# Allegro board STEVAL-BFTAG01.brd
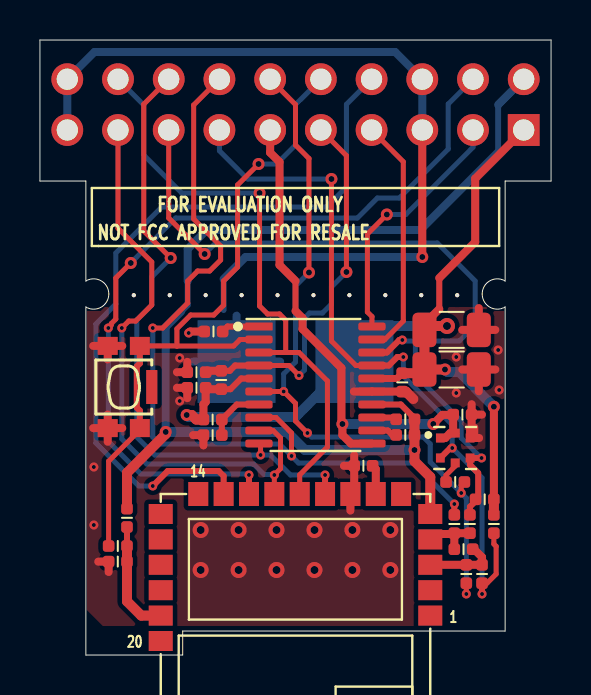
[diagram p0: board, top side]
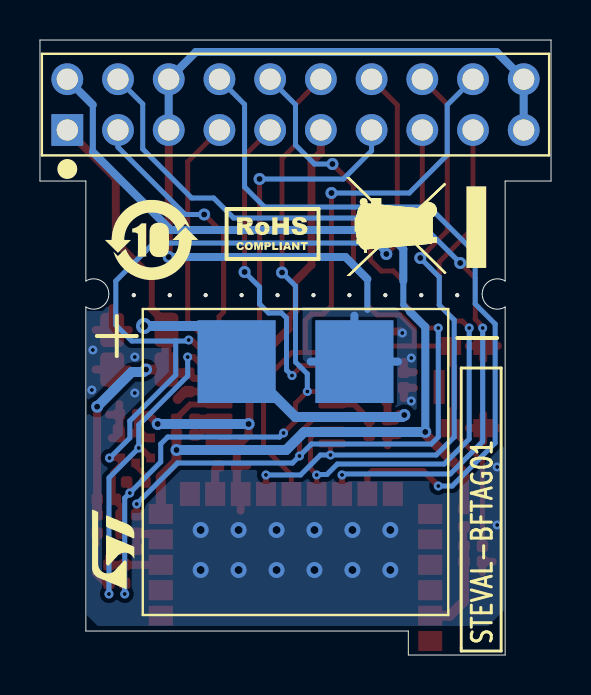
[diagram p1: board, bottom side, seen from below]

Outline 25.6 x 30.75 mm; copper layers: TOP, BOTTOM. Coordinates in mm from the lower left corner of the outline.
Outline path: 0,30.75 0,23.7 2.3,23.7 2.3,18.7 arc(3.06,18.71) 3.45,18.05 arc(3.06,17.39) 2.3,17.4 2.3,0 7.15,0 7.15,1.2 23.3,1.2 23.3,17.4 arc(22.54,17.39) 22.15,18.05 arc(22.54,18.71) 23.3,18.7 23.3,23.7 25.6,23.7 25.6,30.75 0,30.75

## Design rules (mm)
constraint set DEFAULT: min track width 0.4

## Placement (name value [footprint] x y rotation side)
B1  AM-1606C-MEL  [SOLAR_PANEL_AM-1606C-MEL]  12.8 9.65 0 bottom
CB1  100nF  [C_0402]  3.9 4.67 180 top
CH1  100nF  [C_0402]  21.16 12.02 0 top
CM1  10nF  [C_0402]  7.84 14.14 180 top
CM2  100nF  [C_0402]  7.84 13.36 180 top
CM3  100nF  [C_0402]  18.14 13.63 270 top
CS1  220uF  [C_1206_HD]  20.62 14.28 0 top
CS2  220uF  [C_1206_HD]  20.62 16.26 0 top
JSWD  con20-2x10-strip-male  [HDRV20W64P254_10X2_2540X508H838]  24.23 26.25 180 bottom
LOGO1  ST LOGO  [STLOGO12MM]  21.75 5.4 90 bottom
LOGO2  RoHS EU LOGO  [ROHS-EU-LOGO13MM]  16.25 19.1 180 bottom
LOGO3  ROHS_CH_LOGO_10  [ROHS-CH-10-12MM]  22.35 18.75 180 bottom
LOGO4  WEEE LOGO  [WEEE12MM]  3.25 18.95 90 bottom
NOREF  -  [unnamed]  4.7 17.99 0 top
NOREF#2  -  [unnamed]  20.9 17.99 0 top
NOREF#3  -  [unnamed]  19.1 17.99 0 top
NOREF#4  -  [#2]  2.8 15.5 0 top
NOREF#5  -  [#2]  6.05 0.7 90 top
NOREF#6  -  [#2]  19.55 1.97 90 top
NOREF#7  -  [unnamed]  11.9 17.99 0 top
NOREF#8  -  [unnamed]  6.5 17.99 0 top
NOREF#9  -  [#2]  6.05 7.05 0 top
NOREF#10  -  [unnamed]  13.7 17.99 0 top
NOREF#11  -  [unnamed]  10.1 17.99 0 top
NOREF#12  -  [unnamed]  15.5 17.99 0 top
NOREF#13  -  [#2]  19.55 7.05 90 top
NOREF#14  -  [#2]  5.6 11.3 90 top
NOREF#15  -  [unnamed]  17.3 17.99 0 top
NOREF#16  -  [unnamed]  8.3 17.99 0 top
NOREF#17  -  [#2]  10.47 8.05 0 top
NOREF#18  -  [#2]  18.09 8.05 0 top
RB1  0  [R_0402]  3.9 5.45 180 top
RB2  10K  [R_0402]  16.2 9.46 180 top
RB3  0  [R_0402]  20.75 6.55 270 top
RB4  0  [R_0402]  21.53 6.55 270 top
RB5  0  [R_0402]  22.14 4.05 90 top
RB6  0  [R_0402]  21.21 5.29 0 top
RB7  0  [R_0402]  21.35 4.05 90 top
RBLE  47k  [R_0402]  4.36 6.86 270 top
RH1  0  [R_0402]  20.8 8.65 0 top
RM1  10K  [R_0402]  9.08 13.75 270 top
RM2  10K  [R_0402]  8.69 16.18 180 top
RM3  0  [R_0402]  18.3 11.79 0 top
RM4  0  [R_0402]  18.3 11.01 0 top
RSCL  4.7k  [R_0402]  22.73 6.55 90 top
RSDA  4.7k  [R_0402]  22.27 7.79 0 top
RUP1  9.1M  [R_0402]  8.65 11.78 180 top
RUP2  6.2M  [R_0402]  8.65 11 0 top
SW1  miniswitch-KMR211GLFS  [SWITCH_SMT_4_2X2_8MM]  4.2 13.4 270 top
U1  -  [BLUENRG-M2SP]  12.8 2.3 180 top
U2  STM32L031F4P  [SOP20P65_650X640X120L60X24N]  13.8 13.5 270 top
U3  HTS221TR  [PQFN100P200X200X100-6N]  20.8 10.35 0 top

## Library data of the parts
B1 = SOLAR_PANEL
CB1 CH1 CM1-CM3 = CAP: alternate symbols: (c_0402_hd)
CS1 CS2 = CAP
JSWD = CON20A
LOGO1 = LOGO_ST: alternate symbols: (stlogo11mm,STLogo10mm,STLogo9mm,STLogo8mm,STLogo7mm,STLogo6mm,STLogo5mm,stlogo4mm)
LOGO2 = RoHS_EU: alternate symbols: (rohs-eu-logo9mm,RoHS-Eu-Logo7mm,RoHS-Eu-Logo5mm)
LOGO3 = RoHS_CH_10: alternate symbols: (rohs-ch-10-10mm,rohs-ch-10-8mm,rohs-ch-10-6mm,rohs-ch-10-5mm,rohs-ch-10-4mm)
LOGO4 = WEEE: alternate symbols: (weee10mm,weee8mm,weee7mm)
RB1-RB7 RBLE RH1 RM1-RM4 RSCL RSDA RUP1 RUP2 = RES: alternate symbols: (r_0402_hd)
SW1 = PUSHBUTTON-SPST-2
U1 = BLUENRG-M2SP
U2 = STM32L031F4P
U3 = HTS221_0

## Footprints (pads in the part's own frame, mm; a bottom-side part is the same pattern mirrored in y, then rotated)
BLUENRG-M2SP
  rect 1.2x1 smd: 1(-6.75,0.33) 2(-6.75,-0.94) 3(-6.75,-2.21) 4(-6.75,-3.48) 5(-6.75,-4.75) 15(6.75,-4.75) 16(6.75,-3.48) 17(6.75,-2.21) 18(6.75,-0.94) 19(6.75,0.33) 20(6.75,1.6)
  rect 1x1.2 smd: 6(-5.29,-5.75) 7(-4.02,-5.75) 8(-2.75,-5.75) 9(-1.48,-5.75) 10(-0.21,-5.75) 11(1.06,-5.75) 12(2.33,-5.75) 13(3.6,-5.75) 14(4.87,-5.75)
C_0402
  rrect 0.58x0.58 smd: 1(-0.46,0) 2(0.46,0)
C_1206_HD
  rrect 1.2x1.72 smd: 1(-1.36,0) 2(1.36,0)
HDRV20W64P254_10X2_2540X508H838
  rect 1.59x1.59 hole 1.06: 1(0,0)
  round 1.59 hole 1.06: 2(0,2.54) 3(2.54,0) 4(2.54,2.54) 5(5.08,0) 6(5.08,2.54) 7(7.62,0) 8(7.62,2.54) 9(10.16,0) 10(10.16,2.54) 11(12.7,0) 12(12.7,2.54) 13(15.24,0) 14(15.24,2.54) 15(17.78,0) 16(17.78,2.54) 17(20.32,0) 18(20.32,2.54) 19(22.86,0) 20(22.86,2.54)
PQFN100P200X200X100-6N
  rect 0.44x0.45 smd: 1(-0.745,0.5) 2(-0.745,-0.5) 4(0.745,-0.5) 5(0.745,0.5)
  rect 0.45x0.44 smd: 3(0,-0.745) 6(0,0.745)
R_0402
  rrect 0.58x0.58 smd: 1(-0.46,0) 2(0.46,0)
SOLAR_PANEL_AM-1606C-MEL
  rect 3.91x4.14 smd: P+(2.95,-5.02) P-(-2.95,-5.02)
SOP20P65_650X640X120L60X24N
  rect 0.39x1.36 smd: 1(-2.925,-2.83)
  rrect 0.39x1.36 smd: 2(-2.275,-2.83) 3(-1.625,-2.83) 4(-0.975,-2.83) 5(-0.325,-2.83) 6(0.325,-2.83) 7(0.975,-2.83) 8(1.625,-2.83) 9(2.275,-2.83) 10(2.925,-2.83) 11(2.925,2.83) 12(2.275,2.83) 13(1.625,2.83) 14(0.975,2.83) 15(0.325,2.83) 16(-0.325,2.83) 17(-0.975,2.83) 18(-1.625,2.83) 19(-2.275,2.83) 20(-2.925,2.83)
SWITCH_SMT_4_2X2_8MM
  rect 1.7x0.56 smd: (0,1.4)
  rect 0.9x1 smd: 1(-2.055,0.805) 2(2.055,0.805) 3(-2.055,-0.805) 4(2.055,-0.805)
unnamed
  round 0.2 hole 1.1 unplated: (0,0)

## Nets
GND: B1.P- CB1.2 CH1.2 CM1.2 CM2.2 CM3.2 CS1.2 CS2.2 JSWD.5 JSWD.6 JSWD.19 JSWD.20 RB2.2 RM2.2 RUP2.1 SW1.3 SW1.4 U1.8 U2.15(VSS) U3.5
ANATEST1: U1.14
BLE_RST: JSWD.10 RB1.2 SW1.1 SW1.2 U2.2
BLE_TXE: JSWD.18 U1.10 U2.3
BLE_WFE: JSWD.17 U1.11 U2.9
BOOT0: RM2.1 U2.1
BTH: JSWD.16 U1.9 U2.10
I2C_SCL: JSWD.13 RB5.1 RSCL.1 U2.17 U3.2
I2C_SDA: JSWD.15 RB4.1 RSDA.1 U2.18 U3.4
NRST: CB1.1 RB1.1 RBLE.2 U1.19
VBLUE: JSWD.2 RBLE.1 RM3.2 RM4.2 U1.5(VIN) U2.14
VHTS: CH1.1 JSWD.11 U2.11 U3.1(VDD) U3.6
VMID: RUP1.1 RUP2.2 U2.7
VSTOR: B1.P+ CM2.1 CM3.1 CS1.1 CS2.1 JSWD.1 RM1.2 RSCL.2 RSDA.2 RUP1.2 U2.5 U2.16
N01725: JSWD.4 U1.12
N01742: JSWD.8 U1.13
N02299: JSWD.7 U2.19
N07126: RB3.2 RB4.2 RB6.1 U1.4
N07255: RB2.1 U1.7
N07625: RB5.2 RB6.2 RB7.2 U1.3
N14342: RM4.1 U2.12
N14407: RM3.1 U2.13
N16953: JSWD.3 U2.20
N16984: CM1.1 JSWD.9 RM1.1 U2.4
N18701: JSWD.14 RB3.1 U2.8
N18720: JSWD.12 RB7.1 RH1.2 U2.6
N19245: RH1.1 U3.3

Pads without a net: U1 1 2 6 15 16 17 18 20

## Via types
v1: diameter 0.45, hole 0.2, TOP to BOTTOM, 29 vias
v2: diameter 0.6, hole 0.3, TOP to BOTTOM, 17 vias
v3: diameter 0.8, hole 0.4, TOP to BOTTOM, 13 vias

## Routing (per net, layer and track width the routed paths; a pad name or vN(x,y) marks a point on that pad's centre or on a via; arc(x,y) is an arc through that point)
GND: length 73.9
  TOP w0.3: U3.5 21.8,11.11 21.8,11.4
  TOP w0.4: 2.67,15.46 SW1.3 ; SW1.3 4.12,15.46 ; SW1.3 3.4,14.78 ; 6.86,13.36 CM2.2 7.38,12.84 ; 15.22,9.46 RB2.2 ; RB2.2 15.74,9.98 ; RB2.2 15.74,8.44 15.55,8.25 U1.8 15.55,7.22 ; 21.15,16.26 CS2.2 ; CS2.2 22.81,16.26 ; CS2.2 21.98,17.34 ; JSWD.5 v2(19.15,19.9) ; 2.67,11.34 SW1.4 ; SW1.4 3.4,10.67 ; SW1.4 3.4,12.02 ; SW1.4 4.12,11.34 ; 21.15,14.28 CS1.2 ; CS1.2 22.81,14.28 ; CS1.2 21.98,13.19 ; 3.44,4.15 CB1.2 2.92,4.67 ; 8.19,10.48 RUP2.1 7.67,11 ; CM3.2 18.14,13.18 U2.15 15.72,13.18 ; 21.99,10.85 U3.5 21.54,11.3 ; 21.62,11.5 CH1.2 ; CH1.2 22.14,12.02 ; CH1.2 21.62,12.54 ; RM2.2 7.52,16.18 v1(7.45,16.1) ; 6.86,14.14 CM1.2 7.38,14.66
  TOP w0.5: 18.7,12.8 18.33,13.17 CM3.2
  BOTTOM w0.3: 9.2,17.25 9.2,18.8
  BOTTOM w0.4: B1.P- 9.85,16.97 ; B1.P- 12.03,14.67 ; B1.P- 7.67,14.67 ; v2(19.15,19.9) 10.3,19.9 9.2,18.8 ; JSWD.19 JSWD.20 2.73,30.15 17.79,30.15 JSWD.6 JSWD.5
  vias: v1(2.7,9.4) v1(2.7,6.5) v1(7,14.85) v1(7,12.7) v1(20.85,14.9) v1(20.85,13.1) v1(22.95,15.25) v1(23,13.25) v3(8.05,6.25) v3(8.05,4.25) v3(9.95,6.25) v3(9.95,4.25) v3(11.85,6.25) v3(11.85,4.25) v3(13.75,6.25) v3(13.75,4.25) v3(15.65,6.25) v3(15.65,4.25) v3(17.55,6.25) v3(17.55,4.25)
BLE_RST: length 34.4
  TOP w0.25: 6.86,15.45 9.7,15.45 10.02,15.78 U2.2 ; 6.86,15.45 6.86,16.31 7.55,17 8.71,17 9.2,17.49 9.2,18.7 9.9,19.4 9.9,23.5 v2(10.95,24.55) ; 6.86,15.45 6.86,15.46 SW1.1 ; RB1.2 3.44,9.69 5,11.25 SW1.2
  TOP w0.3: SW1.1 5,14.58 4.85,14.42 4.85,12.38 5,12.22 SW1.2
  BOTTOM w0.25: JSWD.10 12.8,27.52 12.8,25.5 11.85,24.55 v2(10.95,24.55)
BLE_TXE: length 30
  TOP w0.25: 12.31,15.12 U2.3 ; 12.31,15.12 12.97,15.12 14.4,13.7 14.4,10.4 13.01,9.01 U1.10 ; 12.31,15.12 12.31,16.74 12,17.05 11.4,17.05 11,17.45 v2(11,23.1)
  BOTTOM w0.25: JSWD.18 5.2,27.5 5.2,25 7.1,23.1 v2(11,23.1)
BLE_WFE: length 29.5
  TOP w0.25: U1.11 v1(11.74,9) 11.74,9.01 12.05,9.32 12.05,10.85 11.67,11.23 U2.9 ; v1(4.1,16.35) 4.45,16.7 4.8,16.7 5.6,17.5 5.6,19.65 3.91,21.34 JSWD.17
  BOTTOM w0.25: v1(4.1,16.35) 4.1,10.8 5.35,9.55 10.7,9.55 11.23,9.03 11.72,9.03 v1(11.74,9)
BOOT0: length 1.9
  TOP w0.3: U2.1 9.4,16.43 RM2.1
BTH: length 31.5
  TOP w0.25: JSWD.16 5.2,27.54 5.2,21.2 v2(6.55,19.85) ; v1(11.05,10) 11.05,10.58 10.97,10.58
  TOP w0.3: v1(14.28,9) U1.9
  BOTTOM w0.25: v2(6.55,19.85) 5.6,18.9 5.6,17.5 4.85,16.75 4.85,10.9 5.75,10 v1(11.05,10) 11.55,10 12.55,9 v1(14.28,9)
I2C_SCL: length 37.4
  TOP w0.25: v2(14.6,23.8) 14.6,15.7 15.82,14.48 16.63,14.48 ; RB5.1 22.39,3.59 22.85,4.05 22.85,5.43 22.73,5.55 RSCL.1
  TOP w0.3: 16.63,14.48 17.48,14.48 17.9,14.9 v1(18.2,14.9) ; v1(22.14,3.05) RB5.1 ; U3.2 20.55,10.35 v1(20.65,10.35)
  BOTTOM w0.25: v1(18.2,14.9) 18.2,13.95 20.65,11.5 v1(20.65,10.35) 22.14,8.86 v1(22.14,3.05) ; JSWD.13 8.99,25.21 10.4,23.8 v2(14.6,23.8)
I2C_SDA: length 40.5
  TOP w0.25: JSWD.15 6.45,21.85 v2(8.25,20.05)
  TOP w0.3: v1(18.15,15.75) 18,15.75 17.38,15.12 U2.18 ; RB4.1 21.53,7.41 21.81,7.69 RSDA.1 21.95,7.92 21.95,9.1 21.54,9.51 U3.4 v1(22.12,9.85)
  BOTTOM w0.25: v1(22.12,9.85) 22.1,9.85 21.1,10.85 21.1,11.7 18.8,14 18.8,15.7 ; 18.8,15.7 21,15.7 21.8,16.5 21.8,18.7 19.9,20.6 8.8,20.6 v2(8.25,20.05) ; 18.8,15.7 18.2,15.7 v1(18.15,15.75)
NRST: length 5.7
  TOP w0.3: RBLE.2 RB1.1
  TOP w0.5: RB1.1 CB1.1 4.36,2.68 5.07,1.97 U1.19
VBLUE: length 56.3
  TOP w0.3: 18.76,11.84 18.07,12.53 U2.14
  TOP w0.4: RM3.2 18.76,11.84
  TOP w0.5: v2(6.3,11.15) 6.3,11.05 4.36,9.11 RBLE.1 ; U1.5 19.55,8.9 18.76,9.69 v2(18.76,10.25) RM4.2 RM3.2
  BOTTOM w0.3: 7.4,18.7 7.4,17.5 7.07,17.18 ; 22.95,27.51 22.95,25.15
  BOTTOM w0.4: 7.07,17.18 6.3,16.4 v2(6.3,11.15) ; 7.4,18.7 7.4,20.3 8.35,21.25 19.05,21.25 22.95,25.15 ; JSWD.2 22.95,27.51
  BOTTOM w0.5: v2(6.3,11.15) 6.3,11.15 12.37,11.15 13.27,10.25 v2(18.76,10.25)
VHTS: length 26
  TOP w0.3: 12.8,18.7 12.8,17.2
  TOP w0.4: 20.7,12.01 20.16,12.01 v2(19.7,11.55) ; 20.7,12.01 20.7,11.2 U3.6 20.54,11.09 20.3,10.85 U3.1 ; 20.7,12.01 CH1.1 ; 16.63,10.58 15.57,10.58 15.15,11 v2(15.15,11.55) 15.1,11.6 15.1,14.35 13.15,16.3 13.15,16.85 12.8,17.2 ; 12.8,18.7 12,19.5 12,24.65 11.53,25.12 JSWD.11
  BOTTOM w0.5: v2(19.7,11.55) v2(15.15,11.55)
VMID: length 3
  TOP w0.3: U2.7 9.86,12.53 RUP1.1 RUP2.2
VSTOR: length 48.2
  TOP w0.3: RM1.2 9.54,13.29 10.07,13.83 U2.5 ; 20,18.85 20,17.3
  TOP w0.35: U2.16 17.88,13.83 CM3.1
  TOP w0.4: 20,17.3 19.26,16.56 CS2.1 ; RM1.2 8.37,13.29 CM2.1 8.3,12.64 8.19,12.53 RUP1.2 ; RSDA.2 v2(22.73,12.42) ; JSWD.1 21.8,23.82 21.8,20.65 20,18.85
  TOP w0.5: RSDA.2 RSCL.2 ; v2(7.35,12) 7.6,12 7.82,11.78 RUP1.2 ; CS1.1 v2(20.29,14.28) ; CS1.1 19.07,14.09 CM3.1 ; CS1.1 CS2.1 19.45,16.45 v3(20.39,16.45)
  BOTTOM w0.5: v2(7.35,12) 7.45,11.9 12.8,11.9 15.57,14.67 B1.P+ 17.53,16.45 v3(20.39,16.45) ; v2(22.73,12.42) 21,14.15 20.41,14.15 v2(20.29,14.28)
N01725: length 40.3
  TOP w0.25: v1(3.42,16.35) 3.57,16.5 3.57,16.57 3.8,16.8 3.8,18.85 v2(4.55,19.6)
  TOP w0.3: v1(10.47,9) U1.12
  BOTTOM w0.25: v2(4.55,19.6) 6.8,21.85 15.9,21.85 16.9,22.85 18,22.85 20.45,25.3 20.45,27.55 JSWD.4 ; v1(3.42,16.35) 3.42,10.68 5.05,9.05 10.42,9.05 v1(10.47,9)
N01742: length 37.3
  TOP w0.3: U1.13 9.2,8.95 8.95,9.2 6.4,9.2 v1(5.65,8.45)
  BOTTOM w0.25: JSWD.8 15.35,27.53 15.35,23.4 14.35,22.4 6.1,22.4 3.8,20.1 3.8,17.55 2.8,16.55 2.8,10.6 4.95,8.45 v1(5.65,8.45)
N02299: length 12.2
  TOP w0.25: U2.19 17.27,15.78 18.2,16.7 18.2,24.66 JSWD.7
N07126: length 2.9
  TOP w0.4: U1.4 19.82,6.05 20.71,6.05 RB3.2 ; RB4.2 RB3.2 ; RB3.2 RB6.1
N07255: length 1.5
  TOP w0.4: U1.7 16.82,9.3 RB2.1
N07625: length 3.6
  TOP w0.4: RB6.2 21.74,5.29 22.14,4.89 RB5.2 RB7.2 U1.3
N14342: length 1.3
  TOP w0.3: RM4.1 17.83,11.01 17.64,11.01 17.42,11.23 U2.12
N14407: length 1.2
  TOP w0.3: U2.13 17.75,11.88 RM3.1
N16953: length 12.7
  TOP w0.25: v2(17.38,22.03) 16.4,21.05 16.4,17.15 16.63,16.92 U2.20
  BOTTOM w0.25: JSWD.3 21.69,25.39 18.32,22.03 v2(17.38,22.03)
N16984: length 19.2
  TOP w0.25: 10.97,14.48 12.47,14.48 v1(12.97,13.98) ; v2(15.35,19.15) 15.35,24.97 JSWD.9
  TOP w0.3: 10.97,14.48 9.77,14.48 9.51,14.21 RM1.1
  TOP w0.4: CM1.1 8.37,14.21 RM1.1
  BOTTOM w0.25: v1(12.97,13.98) 13.25,14.25 13.25,16.85 13.5,17.1 14.15,17.1 14.6,17.55 14.6,18.4 v2(15.35,19.15)
N18701: length 41.2
  TOP w0.25: U2.8 11.82,11.88 12.6,11.1 v1(12.6,9.95) ; v1(5.65,16.35) 6.15,16.35 7.4,17.6 7.4,18.7 7.9,19.2 8.5,19.2 9.05,19.75 9.05,20.45 7.7,21.8 7.7,27.5 JSWD.14
  TOP w0.3: v1(20.75,7.55) RB3.1
  BOTTOM w0.25: v1(5.65,16.35) 5.65,10.9 6,10.55 12,10.55 v1(12.6,9.95) 12.95,9.6 18.7,9.6 v1(20.75,7.55)
N18720: length 36.5
  TOP w0.25: v1(13.4,11.1) 12.8,11.7 12.8,12.58 v1(12.21,13.18) U2.6 ; v1(21.1,8.1) 21.1,8.49 RH1.2 ; v1(21.35,3.05) RB7.1 ; JSWD.12 12.8,27.52 12.8,25.5 13.47,24.82 v2(13.47,19.12)
  BOTTOM w0.25: v1(13.4,11.1) 13.6,10.9 19.2,10.9 19.55,10.55 19.55,9.65 v1(21.1,8.1) 21.35,7.84 v1(21.35,3.05) ; v2(13.47,19.12) 12.8,18.45 12.8,14.65 12.21,14.06 v1(12.21,13.18)
N19245: length 1.1
  TOP w0.25: U3.3 20.8,9.45 20.34,8.99 RH1.1

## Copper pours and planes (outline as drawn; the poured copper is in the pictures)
GND on TOP: 3.25,17.4 22.35,17.4 22.55,17.2 23.25,17.2 23.25,2 22.7,1.45 3.15,1.45 2.35,2.25 2.35,17.2 3.05,17.2 ; 10 cut-outs
GND on BOTTOM: 2.35,17.2 2.35,2.25 3.15,1.45 22.7,1.45 23.25,2 23.25,17.2 22.45,17.2 22.25,17.4 3.25,17.4 3.05,17.2 ; 6 cut-outs

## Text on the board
Ref Des/Silkscreen Bottom: STEVAL-BFTAG01
Ref Des/Silkscreen Top: NOT FCC APPROVED FOR RESALE | FOR EVALUATION ONLY
DISPLAY_BOTTOM: FIGURE | FINISHED_SIZE | 0.2 | 0.3 | 0.4 | 1.06 | 1.1 | DRILL CHART: TOP to BOTTOM | ALL UNITS ARE IN MILLIMETERS | PLATED | NON-PLATED | QTY | 29 | 17 | 13 | 20 | 10
